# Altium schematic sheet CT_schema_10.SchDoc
size 391 x 238 mm
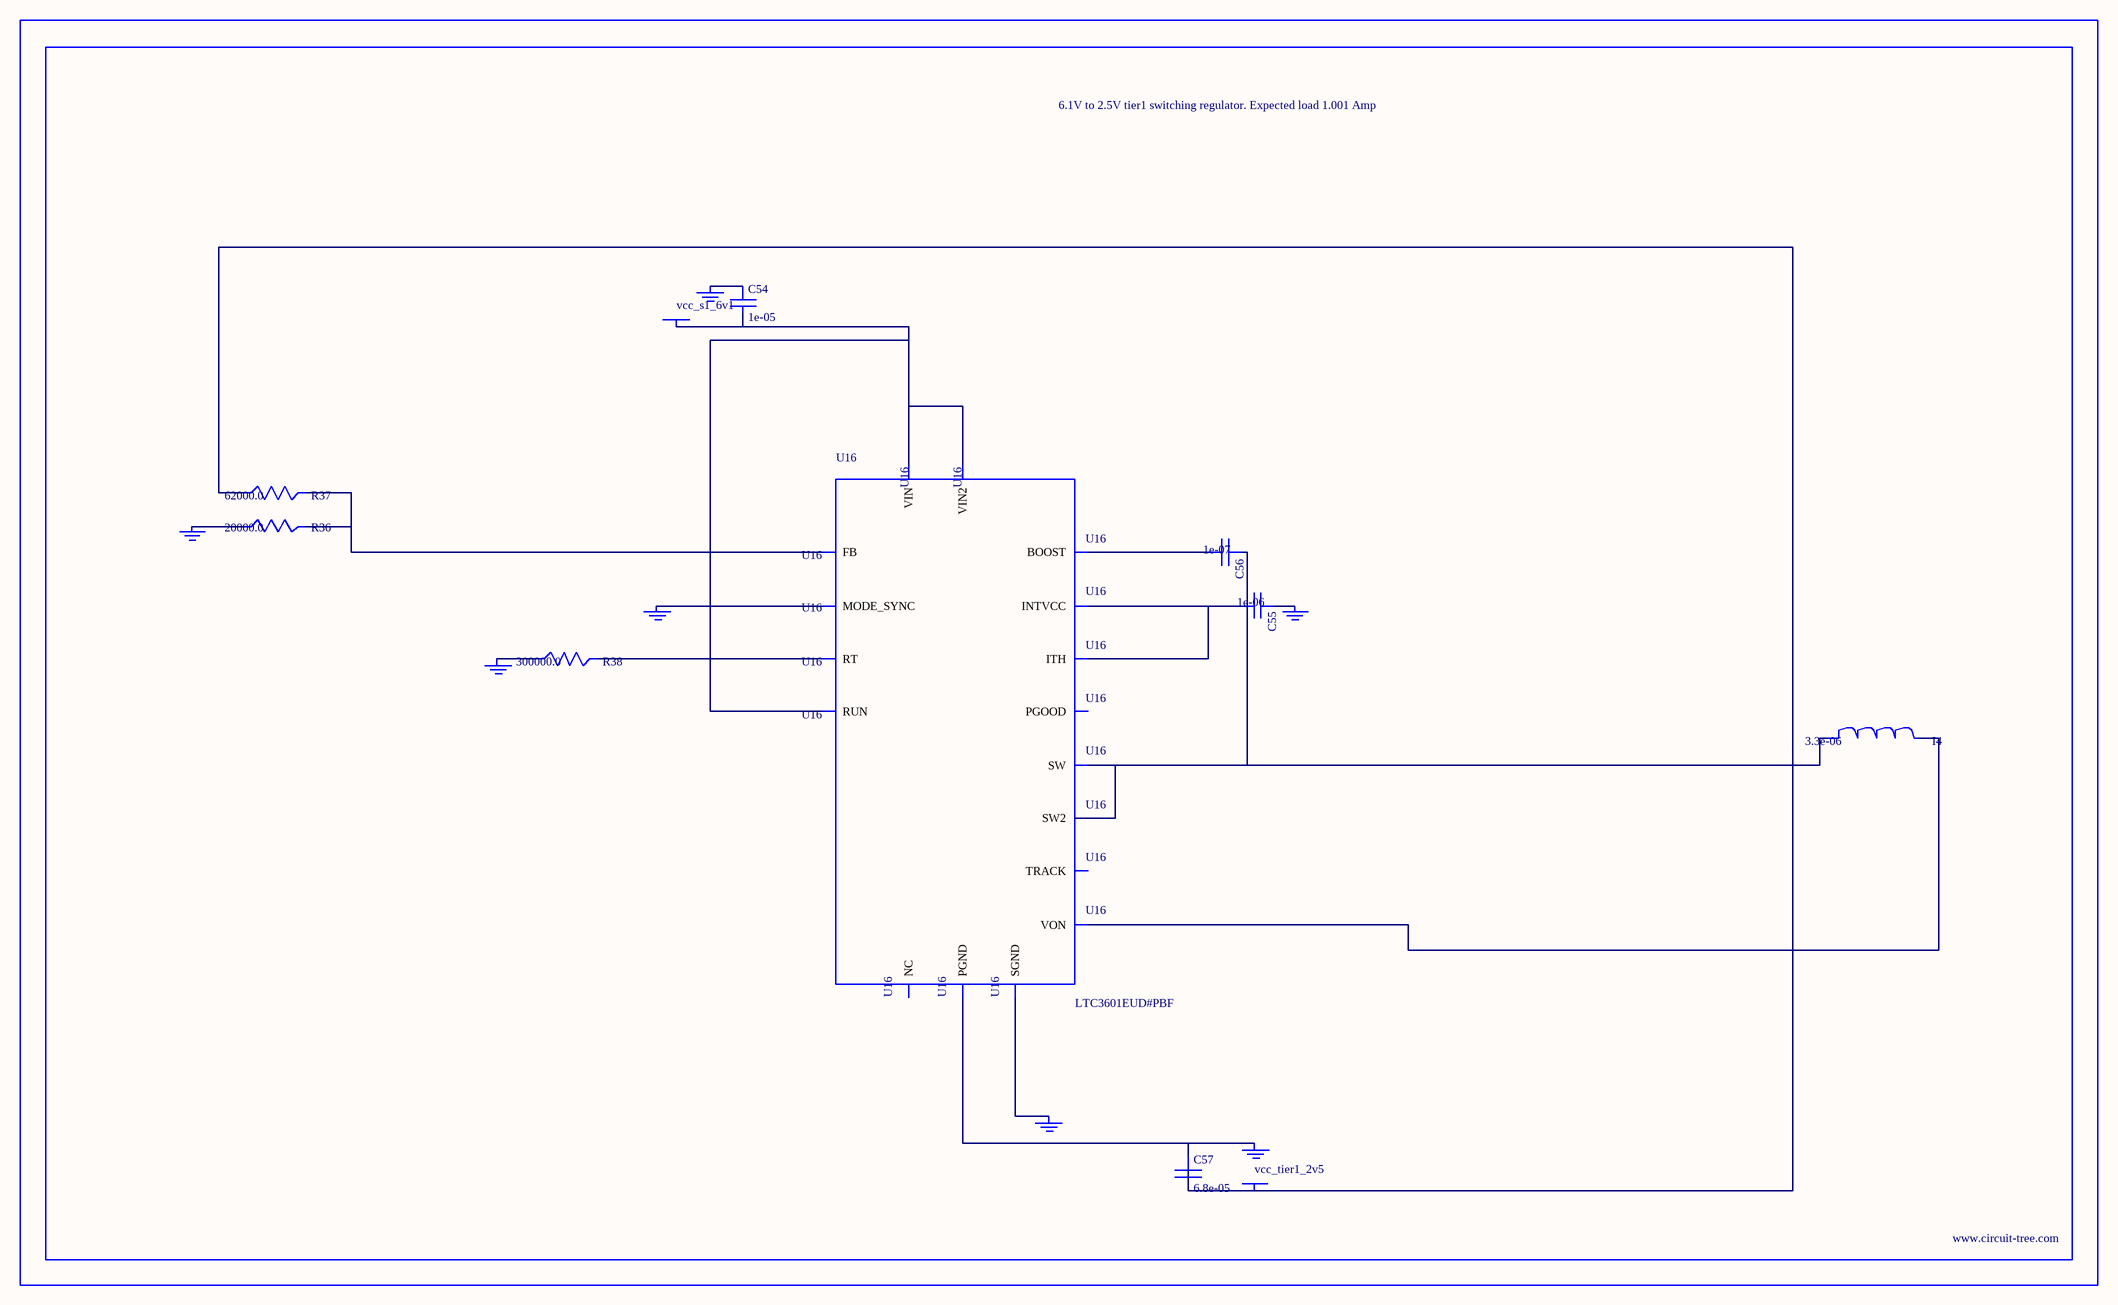
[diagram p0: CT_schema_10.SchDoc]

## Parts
BORDER9  (no value)
C54  1e-05  [C0805]
C55  1e-06  [C0603]
C56  1e-07  [C0402]
C57  6.8e-05  [2220]
GND_INSTANCE_9_0  (no value)
GND_INSTANCE_9_1  (no value)
GND_INSTANCE_9_2  (no value)
GND_INSTANCE_9_3  (no value)
GND_INSTANCE_9_4  (no value)
GND_INSTANCE_9_5  (no value)
GND_INSTANCE_9_6  (no value)
I4  3.3e-06  [WE-HCI_7030/7040/7050]
POWER_INSTANCE_9_0  vcc_s1_6v1
POWER_INSTANCE_9_1  vcc_tier1_2v5
R36  20000.0  [R0603]
R37  62000.0  [R0603]
R38  300000.0  [R0603]
U16  LTC3601EUD#PBF  [QFN-16_EP]

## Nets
NetC54_1: C54.1 GND_INSTANCE_9_5.0(GND)
NetC54_2: C54.2 POWER_INSTANCE_9_0.0(PWR) U16.14(RUN) U16.15(VIN) U16.16(VIN2)
NetC55_1: C55.1 GND_INSTANCE_9_1.0(GND)
NetC55_2: C55.2 U16.7(INTVCC) U16.12(ITH)
NetC56_1: C56.1 I4.1 U16.3(SW) U16.4(SW2)
NetC56_2: C56.2 U16.6(BOOST)
NetC57_1: C57.1 GND_INSTANCE_9_6.0(GND) U16.17(PGND)
NetC57_2: C57.2 I4.2 POWER_INSTANCE_9_1.0(PWR) R37.1 U16.8(VON)
NetGND_INSTANCE_9_0_0: GND_INSTANCE_9_0.0(GND) U16.1(MODE_SYNC)
NetGND_INSTANCE_9_2_0: GND_INSTANCE_9_2.0(GND) U16.9(SGND)
NetGND_INSTANCE_9_3_0: GND_INSTANCE_9_3.0(GND) R38.1
NetGND_INSTANCE_9_4_0: GND_INSTANCE_9_4.0(GND) R36.1
NetR36_2: R36.2 R37.2 U16.11(FB)
NetR38_2: R38.2 U16.10(RT)

Not connected (* = marked no-connect by the designer): U16 2(PGOOD) 5(NC) 13(TRACK)

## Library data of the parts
BORDER9 = BORDER_PAGE9
C54 = C0805C106K8RACTU
C55 = C0603C105K3RACTU
C56 = C0402C104K3RACTU
C57 = C5750X5R1A686M
GND_INSTANCE_9_0-GND_INSTANCE_9_6 = GND
I4 = 744314330
POWER_INSTANCE_9_0 POWER_INSTANCE_9_1 = PWR
R36 = RC0603JR-0720KL
R37 = RC0603JR-0762KL
R38 = RC0603JR-07300KL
